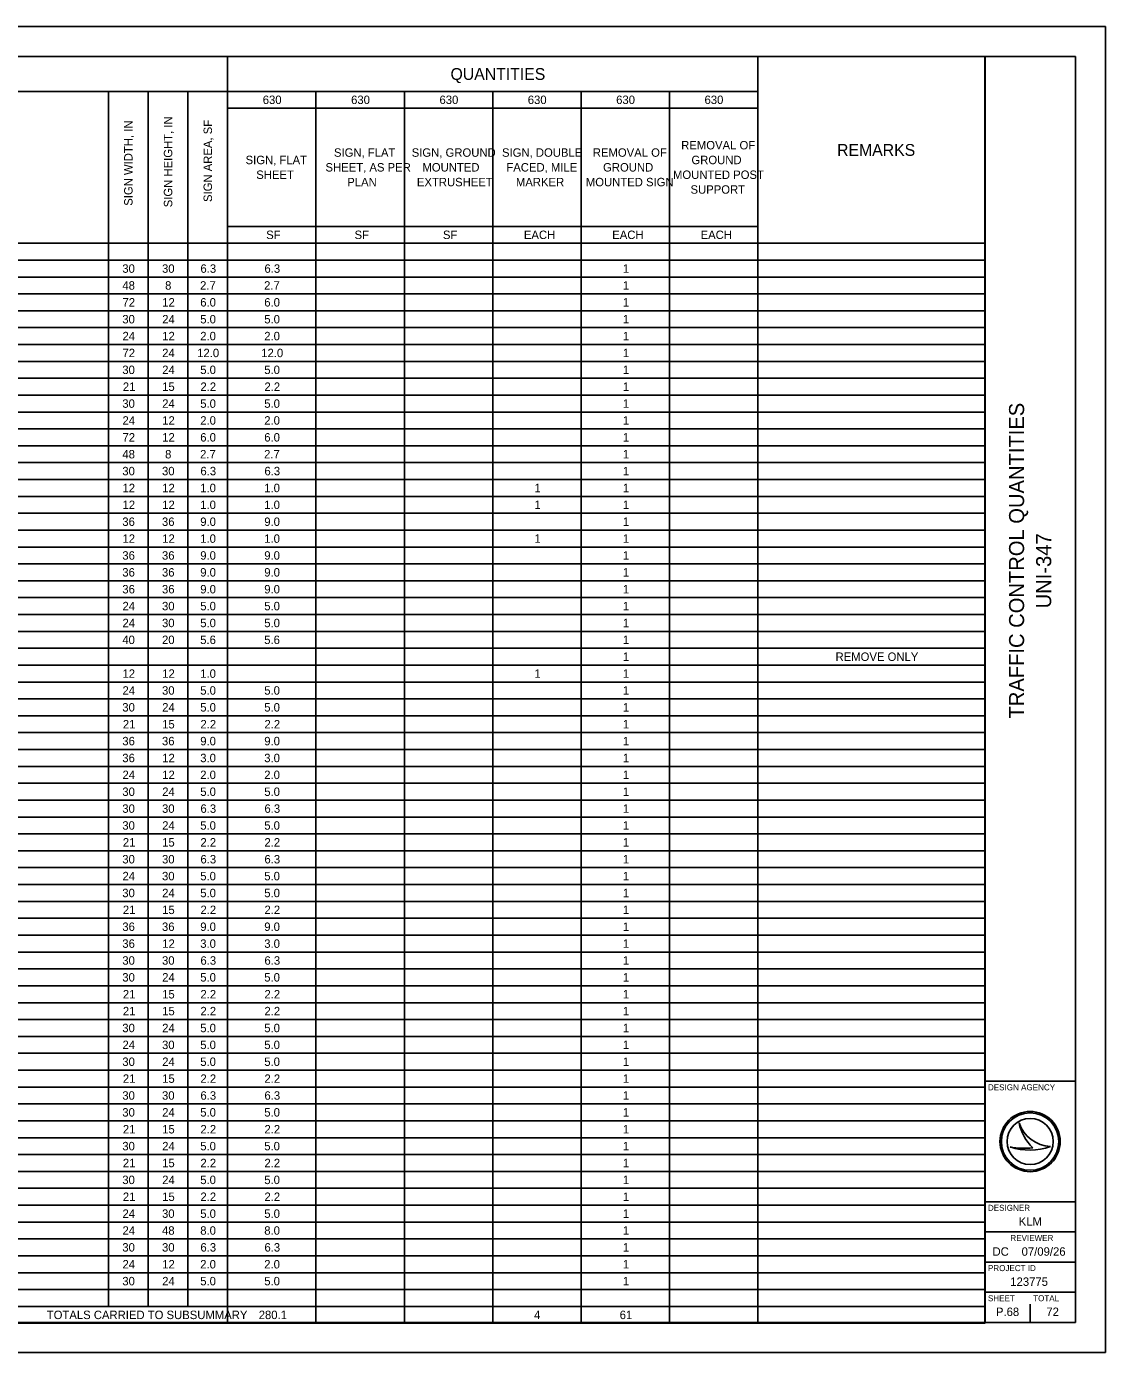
# Model space of a CAD drawing. Extents: x 0 to 34, y 0 to 22.
# Drawn here: x 16.1 to 34, y 0 to 22 of the extents above; entities that cross this region are included whole.
import ezdxf

# ---------------------------------------------------------------- set-up
doc = ezdxf.new("R2010")
doc.units = 0
for name, color, linetype in [('SH_Border', 7, 'Continuous'), ('SH_Cut_Line', 7, 'Continuous'), ('SH_Data', 7, 'Continuous'), ('SH_Text', 7, 'Continuous')]:
    doc.layers.add(name, color=color, linetype=linetype)

msp = doc.modelspace()

# ---------------------------------------------------------------- linework, layer by layer
at = {"layer": 'SH_Border'}
for p, q in [((32, 0.5), (32, 21.5)), ((32, 4.5), (33.5, 4.5)), ((32, 2.5), (33.5, 2.5)), ((32, 2), (33.5, 2)), ((32, 1.5), (33.5, 1.5)), ((32, 1), (33.5, 1))]:
    msp.add_line(p, q, dxfattribs=at)
msp.add_lwpolyline([(1.5, 21.5), (33.5, 21.5), (33.5, 0.5), (1.5, 0.5)], close=True, dxfattribs=at)
at = {"layer": 'SH_Cut_Line'}
msp.add_lwpolyline([(0, 0), (34, 0), (34, 22), (0, 22)], close=True, dxfattribs=at)
at = {"layer": 'SH_Data'}
for p, q in [((1.5, 21.5), (32.004, 21.5)), ((19.436, 21.5), (19.436, 0.484)), ((28.232, 21.5), (28.232, 0.484)), ((32.004, 21.5), (32.004, 0.484)), ((1.5, 20.924), (28.232, 20.924)), ((17.46, 20.924), (17.46, 0.764)), ((18.119, 20.924), (18.119, 0.764)), ((18.778, 20.924), (18.778, 0.764)), ((20.902, 20.924), (20.902, 0.484)), ((22.368, 20.924), (22.368, 0.484)), ((23.834, 20.924), (23.834, 0.484)), ((25.3, 20.924), (25.3, 0.484)), ((26.766, 20.924), (26.766, 0.484)), ((19.436, 20.644), (28.232, 20.644)), ((19.436, 18.684), (28.232, 18.684)), ((1.5, 18.404), (32.004, 18.404)), ((1.5, 18.124), (32.004, 18.124)), ((1.5, 17.844), (32.004, 17.844)), ((1.5, 17.564), (32.004, 17.564)), ((1.5, 17.284), (32.004, 17.284)), ((1.5, 17.004), (32.004, 17.004)), ((1.5, 16.724), (32.004, 16.724)), ((1.5, 16.444), (32.004, 16.444)), ((1.5, 16.164), (32.004, 16.164)), ((1.5, 15.884), (32.004, 15.884)), ((1.5, 15.604), (32.004, 15.604)), ((1.5, 15.324), (32.004, 15.324)), ((1.5, 15.044), (32.004, 15.044)), ((1.5, 14.764), (32.004, 14.764)), ((1.5, 14.484), (32.004, 14.484)), ((1.5, 14.204), (32.004, 14.204)), ((1.5, 13.924), (32.004, 13.924)), ((1.5, 13.644), (32.004, 13.644)), ((1.5, 13.364), (32.004, 13.364)), ((1.5, 13.084), (32.004, 13.084)), ((1.5, 12.804), (32.004, 12.804)), ((1.5, 12.524), (32.004, 12.524)), ((1.5, 12.244), (32.004, 12.244)), ((1.5, 11.964), (32.004, 11.964)), ((1.5, 11.684), (32.004, 11.684)), ((1.5, 11.404), (32.004, 11.404)), ((1.5, 11.124), (32.004, 11.124)), ((1.5, 10.844), (32.004, 10.844)), ((1.5, 10.564), (32.004, 10.564)), ((1.5, 10.284), (32.004, 10.284)), ((1.5, 10.004), (32.004, 10.004)), ((1.5, 9.724), (32.004, 9.724)), ((1.5, 9.444), (32.004, 9.444)), ((1.5, 9.164), (32.004, 9.164)), ((1.5, 8.884), (32.004, 8.884)), ((1.5, 8.604), (32.004, 8.604)), ((1.5, 8.324), (32.004, 8.324)), ((1.5, 8.044), (32.004, 8.044)), ((1.5, 7.764), (32.004, 7.764)), ((1.5, 7.484), (32.004, 7.484)), ((1.5, 7.204), (32.004, 7.204)), ((1.5, 6.924), (32.004, 6.924)), ((1.5, 6.644), (32.004, 6.644)), ((1.5, 6.364), (32.004, 6.364)), ((1.5, 6.084), (32.004, 6.084)), ((1.5, 5.804), (32.004, 5.804)), ((1.5, 5.524), (32.004, 5.524)), ((1.5, 5.244), (32.004, 5.244)), ((1.5, 4.964), (32.004, 4.964)), ((1.5, 4.684), (32.004, 4.684)), ((1.5, 4.404), (32.004, 4.404)), ((1.5, 4.124), (32.004, 4.124)), ((1.5, 3.844), (32.004, 3.844)), ((32.567, 3.81), (32.567, 3.81)), ((1.5, 3.564), (32.004, 3.564)), ((32.417, 3.41), (32.417, 3.41)), ((32.75, 3.5), (32.75, 3.5)), ((33.087, 3.419), (33.087, 3.419)), ((1.5, 3.284), (32.004, 3.284)), ((1.5, 3.004), (32.004, 3.004)), ((1.5, 2.724), (32.004, 2.724)), ((1.5, 2.444), (32.004, 2.444)), ((1.5, 2.164), (32.004, 2.164)), ((1.5, 1.884), (32.004, 1.884)), ((1.5, 1.604), (32.004, 1.604)), ((1.5, 1.324), (32.004, 1.324)), ((1.5, 1.044), (32.004, 1.044)), ((1.5, 0.764), (32.004, 0.764)), ((32.375, 0.675), (32.375, 0.675)), ((32.75, 0.5), (32.75, 0.8)), ((1.5, 0.484), (32.004, 0.484))]:
    msp.add_line(p, q, dxfattribs=at)
for radius in [0.5, 0.477, 0.477, 0.382]:
    msp.add_circle((32.75, 3.5), radius, dxfattribs=at)
for centre, radius, start, end in [((33.116, 3.998), 0.58, 198.9257, 198.9319), ((33.347, 3.97), 0.796, 191.6379, 191.6421), ((33.116, 3.998), 0.58, 198.9319, 267.1657), ((33.347, 3.97), 0.796, 191.6421, 226.0947), ((32.739, 4.37), 1.013, 251.4576, 290.0832), ((32.648, 4.654), 1.266, 259.4964, 259.4995), ((32.739, 4.37), 1.013, 251.4527, 251.4576), ((32.648, 4.654), 1.266, 259.4995, 276.6672)]:
    msp.add_arc(centre, radius, start, end, dxfattribs=at)

# ---------------------------------------------------------------- texts
for s, p in [('TRAFFIC CONTROL QUANTITIES', (32.65, 10.519)), ('UNI-347', (33.1, 12.346))]:
    msp.add_text(s, height=0.25, rotation=90, dxfattribs=at).set_placement(p)
for s, height, p in [('DESIGN AGENCY', 0.1, (32.05, 4.35)), ('DESIGNER', 0.1, (32.05, 2.35)), ('KLM', 0.14, (32.561, 2.105)), ('REVIEWER', 0.1, (32.422, 1.85)), ('DC', 0.14, (32.126, 1.605)), ('07/09/26', 0.14, (32.609, 1.605)), ('PROJECT ID', 0.1, (32.05, 1.35)), ('123775', 0.14, (32.421, 1.105)), ('SHEET', 0.1, (32.05, 0.85)), ('TOTAL', 0.1, (32.8, 0.85)), ('P.68', 0.14, (32.183, 0.605)), ('72', 0.14, (33.019, 0.605))]:
    msp.add_text(s, height=height, dxfattribs=at).set_placement(p)
at = {"layer": 'SH_Text'}
for s, height, p in [('QUANTITIES', 0.196, (23.134, 21.114)), ('630', 0.14, (20.019, 20.714)), ('630', 0.14, (21.485, 20.714)), ('630', 0.14, (22.951, 20.714)), ('630', 0.14, (24.416, 20.714)), ('630', 0.14, (25.882, 20.714)), ('630', 0.14, (27.348, 20.714)), ('REMOVAL OF ', 0.14, (26.961, 19.961)), ('REMARKS', 0.196, (29.547, 19.854)), ('SIGN, FLAT ', 0.14, (19.734, 19.716)), ('SIGN, FLAT ', 0.14, (21.2, 19.839)), ('SIGN, GROUND ', 0.14, (22.49, 19.839)), ('SIGN, DOUBLE ', 0.14, (23.988, 19.839)), ('REMOVAL OF ', 0.14, (25.495, 19.839)), ('GROUND ', 0.14, (27.131, 19.716)), ('SHEET', 0.14, (19.911, 19.471)), ('SHEET, AS PER ', 0.14, (21.06, 19.594)), ('MOUNTED ', 0.14, (22.668, 19.594)), ('FACED, MILE ', 0.14, (24.061, 19.594)), ('GROUND ', 0.14, (25.665, 19.594)), ('MOUNTED POST ', 0.14, (26.825, 19.471)), ('PLAN', 0.14, (21.421, 19.349)), ('EXTRUSHEET', 0.14, (22.576, 19.349)), ('MARKER', 0.14, (24.219, 19.349)), ('MOUNTED SIGN', 0.14, (25.379, 19.349)), ('SUPPORT', 0.14, (27.116, 19.226)), ('SF', 0.14, (20.076, 18.474)), ('SF', 0.14, (21.542, 18.474)), ('SF', 0.14, (23.008, 18.474)), ('EACH', 0.14, (24.351, 18.474)), ('EACH', 0.14, (25.817, 18.474)), ('EACH', 0.14, (27.283, 18.474)), ('30', 0.14, (17.689, 17.914)), ('30', 0.14, (18.348, 17.914)), ('6.3', 0.14, (18.985, 17.914)), ('6.3', 0.14, (20.047, 17.914)), ('1', 0.14, (25.992, 17.914)), ('48', 0.14, (17.69, 17.634)), ('8', 0.14, (18.399, 17.634)), ('2.7', 0.14, (18.979, 17.634)), ('2.7', 0.14, (20.041, 17.634)), ('1', 0.14, (25.992, 17.634)), ('72', 0.14, (17.692, 17.354)), ('12', 0.14, (18.351, 17.354)), ('6.0', 0.14, (18.982, 17.354)), ('6.0', 0.14, (20.044, 17.354)), ('1', 0.14, (25.992, 17.354)), ('30', 0.14, (17.689, 17.074)), ('24', 0.14, (18.351, 17.074)), ('5.0', 0.14, (18.982, 17.074)), ('5.0', 0.14, (20.044, 17.074)), ('1', 0.14, (25.992, 17.074)), ('24', 0.14, (17.692, 16.794)), ('12', 0.14, (18.351, 16.794)), ('2.0', 0.14, (18.982, 16.794)), ('2.0', 0.14, (20.044, 16.794)), ('1', 0.14, (25.992, 16.794)), ('72', 0.14, (17.692, 16.514)), ('24', 0.14, (18.351, 16.514)), ('12.0', 0.14, (18.931, 16.514)), ('12.0', 0.14, (19.994, 16.514)), ('1', 0.14, (25.992, 16.514)), ('30', 0.14, (17.689, 16.234)), ('24', 0.14, (18.351, 16.234)), ('5.0', 0.14, (18.982, 16.234)), ('5.0', 0.14, (20.044, 16.234)), ('1', 0.14, (25.992, 16.234)), ('21', 0.14, (17.698, 15.954)), ('15', 0.14, (18.35, 15.954)), ('2.2', 0.14, (18.985, 15.954)), ('2.2', 0.14, (20.047, 15.954)), ('1', 0.14, (25.992, 15.954)), ('30', 0.14, (17.689, 15.674)), ('24', 0.14, (18.351, 15.674)), ('5.0', 0.14, (18.982, 15.674)), ('5.0', 0.14, (20.044, 15.674)), ('1', 0.14, (25.992, 15.674)), ('24', 0.14, (17.692, 15.394)), ('12', 0.14, (18.351, 15.394)), ('2.0', 0.14, (18.982, 15.394)), ('2.0', 0.14, (20.044, 15.394)), ('1', 0.14, (25.992, 15.394)), ('72', 0.14, (17.692, 15.114)), ('12', 0.14, (18.351, 15.114)), ('6.0', 0.14, (18.982, 15.114)), ('6.0', 0.14, (20.044, 15.114)), ('1', 0.14, (25.992, 15.114)), ('48', 0.14, (17.69, 14.834)), ('8', 0.14, (18.399, 14.834)), ('2.7', 0.14, (18.979, 14.834)), ('2.7', 0.14, (20.041, 14.834)), ('1', 0.14, (25.992, 14.834)), ('30', 0.14, (17.689, 14.554)), ('30', 0.14, (18.348, 14.554)), ('6.3', 0.14, (18.985, 14.554)), ('6.3', 0.14, (20.047, 14.554)), ('1', 0.14, (25.992, 14.554)), ('12', 0.14, (17.692, 14.274)), ('12', 0.14, (18.351, 14.274)), ('1.0', 0.14, (18.982, 14.274)), ('1.0', 0.14, (20.044, 14.274)), ('1', 0.14, (24.526, 14.274)), ('1', 0.14, (25.992, 14.274)), ('12', 0.14, (17.692, 13.994)), ('12', 0.14, (18.351, 13.994)), ('1.0', 0.14, (18.982, 13.994)), ('1.0', 0.14, (20.044, 13.994)), ('1', 0.14, (24.526, 13.994)), ('1', 0.14, (25.992, 13.994)), ('36', 0.14, (17.689, 13.714)), ('36', 0.14, (18.347, 13.714)), ('9.0', 0.14, (18.982, 13.714)), ('9.0', 0.14, (20.044, 13.714)), ('1', 0.14, (25.992, 13.714)), ('12', 0.14, (17.692, 13.434)), ('12', 0.14, (18.351, 13.434)), ('1.0', 0.14, (18.982, 13.434)), ('1.0', 0.14, (20.044, 13.434)), ('1', 0.14, (24.526, 13.434)), ('1', 0.14, (25.992, 13.434)), ('36', 0.14, (17.689, 13.154)), ('36', 0.14, (18.347, 13.154)), ('9.0', 0.14, (18.982, 13.154)), ('9.0', 0.14, (20.044, 13.154)), ('1', 0.14, (25.992, 13.154)), ('36', 0.14, (17.689, 12.874)), ('36', 0.14, (18.347, 12.874)), ('9.0', 0.14, (18.982, 12.874)), ('9.0', 0.14, (20.044, 12.874)), ('1', 0.14, (25.992, 12.874)), ('36', 0.14, (17.689, 12.594)), ('36', 0.14, (18.347, 12.594)), ('9.0', 0.14, (18.982, 12.594)), ('9.0', 0.14, (20.044, 12.594)), ('1', 0.14, (25.992, 12.594)), ('24', 0.14, (17.692, 12.314)), ('30', 0.14, (18.348, 12.314)), ('5.0', 0.14, (18.982, 12.314)), ('5.0', 0.14, (20.044, 12.314)), ('1', 0.14, (25.992, 12.314)), ('24', 0.14, (17.692, 12.034)), ('30', 0.14, (18.348, 12.034)), ('5.0', 0.14, (18.982, 12.034)), ('5.0', 0.14, (20.044, 12.034)), ('1', 0.14, (25.992, 12.034)), ('40', 0.14, (17.689, 11.754)), ('20', 0.14, (18.348, 11.754)), ('5.6', 0.14, (18.981, 11.754)), ('5.6', 0.14, (20.043, 11.754)), ('1', 0.14, (25.992, 11.754)), ('1', 0.14, (25.992, 11.474)), ('REMOVE ONLY', 0.14, (29.522, 11.474)), ('12', 0.14, (17.692, 11.194)), ('12', 0.14, (18.351, 11.194)), ('1.0', 0.14, (18.982, 11.194)), ('1', 0.14, (24.526, 11.194)), ('1', 0.14, (25.992, 11.194)), ('24', 0.14, (17.692, 10.914)), ('30', 0.14, (18.348, 10.914)), ('5.0', 0.14, (18.982, 10.914)), ('5.0', 0.14, (20.044, 10.914)), ('1', 0.14, (25.992, 10.914)), ('30', 0.14, (17.689, 10.634)), ('24', 0.14, (18.351, 10.634)), ('5.0', 0.14, (18.982, 10.634)), ('5.0', 0.14, (20.044, 10.634)), ('1', 0.14, (25.992, 10.634)), ('21', 0.14, (17.698, 10.354)), ('15', 0.14, (18.35, 10.354)), ('2.2', 0.14, (18.985, 10.354)), ('2.2', 0.14, (20.047, 10.354)), ('1', 0.14, (25.992, 10.354)), ('36', 0.14, (17.689, 10.074)), ('36', 0.14, (18.347, 10.074)), ('9.0', 0.14, (18.982, 10.074)), ('9.0', 0.14, (20.044, 10.074)), ('1', 0.14, (25.992, 10.074)), ('36', 0.14, (17.689, 9.794)), ('12', 0.14, (18.351, 9.794)), ('3.0', 0.14, (18.982, 9.794)), ('3.0', 0.14, (20.044, 9.794)), ('1', 0.14, (25.992, 9.794)), ('24', 0.14, (17.692, 9.514)), ('12', 0.14, (18.351, 9.514)), ('2.0', 0.14, (18.982, 9.514)), ('2.0', 0.14, (20.044, 9.514)), ('1', 0.14, (25.992, 9.514)), ('30', 0.14, (17.689, 9.234)), ('24', 0.14, (18.351, 9.234)), ('5.0', 0.14, (18.982, 9.234)), ('5.0', 0.14, (20.044, 9.234)), ('1', 0.14, (25.992, 9.234)), ('30', 0.14, (17.689, 8.954)), ('30', 0.14, (18.348, 8.954)), ('6.3', 0.14, (18.985, 8.954)), ('6.3', 0.14, (20.047, 8.954)), ('1', 0.14, (25.992, 8.954)), ('30', 0.14, (17.689, 8.674)), ('24', 0.14, (18.351, 8.674)), ('5.0', 0.14, (18.982, 8.674)), ('5.0', 0.14, (20.044, 8.674)), ('1', 0.14, (25.992, 8.674)), ('21', 0.14, (17.698, 8.394)), ('15', 0.14, (18.35, 8.394)), ('2.2', 0.14, (18.985, 8.394)), ('2.2', 0.14, (20.047, 8.394)), ('1', 0.14, (25.992, 8.394)), ('30', 0.14, (17.689, 8.114)), ('30', 0.14, (18.348, 8.114)), ('6.3', 0.14, (18.985, 8.114)), ('6.3', 0.14, (20.047, 8.114)), ('1', 0.14, (25.992, 8.114)), ('24', 0.14, (17.692, 7.834)), ('30', 0.14, (18.348, 7.834)), ('5.0', 0.14, (18.982, 7.834)), ('5.0', 0.14, (20.044, 7.834)), ('1', 0.14, (25.992, 7.834)), ('30', 0.14, (17.689, 7.554)), ('24', 0.14, (18.351, 7.554)), ('5.0', 0.14, (18.982, 7.554)), ('5.0', 0.14, (20.044, 7.554)), ('1', 0.14, (25.992, 7.554)), ('21', 0.14, (17.698, 7.274)), ('15', 0.14, (18.35, 7.274)), ('2.2', 0.14, (18.985, 7.274)), ('2.2', 0.14, (20.047, 7.274)), ('1', 0.14, (25.992, 7.274)), ('36', 0.14, (17.689, 6.994)), ('36', 0.14, (18.347, 6.994)), ('9.0', 0.14, (18.982, 6.994)), ('9.0', 0.14, (20.044, 6.994)), ('1', 0.14, (25.992, 6.994)), ('36', 0.14, (17.689, 6.714)), ('12', 0.14, (18.351, 6.714)), ('3.0', 0.14, (18.982, 6.714)), ('3.0', 0.14, (20.044, 6.714)), ('1', 0.14, (25.992, 6.714)), ('30', 0.14, (17.689, 6.434)), ('30', 0.14, (18.348, 6.434)), ('6.3', 0.14, (18.985, 6.434)), ('6.3', 0.14, (20.047, 6.434)), ('1', 0.14, (25.992, 6.434)), ('30', 0.14, (17.689, 6.154)), ('24', 0.14, (18.351, 6.154)), ('5.0', 0.14, (18.982, 6.154)), ('5.0', 0.14, (20.044, 6.154)), ('1', 0.14, (25.992, 6.154)), ('21', 0.14, (17.698, 5.874)), ('15', 0.14, (18.35, 5.874)), ('2.2', 0.14, (18.985, 5.874)), ('2.2', 0.14, (20.047, 5.874)), ('1', 0.14, (25.992, 5.874)), ('21', 0.14, (17.698, 5.594)), ('15', 0.14, (18.35, 5.594)), ('2.2', 0.14, (18.985, 5.594)), ('2.2', 0.14, (20.047, 5.594)), ('1', 0.14, (25.992, 5.594)), ('30', 0.14, (17.689, 5.314)), ('24', 0.14, (18.351, 5.314)), ('5.0', 0.14, (18.982, 5.314)), ('5.0', 0.14, (20.044, 5.314)), ('1', 0.14, (25.992, 5.314)), ('24', 0.14, (17.692, 5.034)), ('30', 0.14, (18.348, 5.034)), ('5.0', 0.14, (18.982, 5.034)), ('5.0', 0.14, (20.044, 5.034)), ('1', 0.14, (25.992, 5.034)), ('30', 0.14, (17.689, 4.754)), ('24', 0.14, (18.351, 4.754)), ('5.0', 0.14, (18.982, 4.754)), ('5.0', 0.14, (20.044, 4.754)), ('1', 0.14, (25.992, 4.754)), ('21', 0.14, (17.698, 4.474)), ('15', 0.14, (18.35, 4.474)), ('2.2', 0.14, (18.985, 4.474)), ('2.2', 0.14, (20.047, 4.474)), ('1', 0.14, (25.992, 4.474)), ('30', 0.14, (17.689, 4.194)), ('30', 0.14, (18.348, 4.194)), ('6.3', 0.14, (18.985, 4.194)), ('6.3', 0.14, (20.047, 4.194)), ('1', 0.14, (25.992, 4.194)), ('30', 0.14, (17.689, 3.914)), ('24', 0.14, (18.351, 3.914)), ('5.0', 0.14, (18.982, 3.914)), ('5.0', 0.14, (20.044, 3.914)), ('1', 0.14, (25.992, 3.914)), ('21', 0.14, (17.698, 3.634)), ('15', 0.14, (18.35, 3.634)), ('2.2', 0.14, (18.985, 3.634)), ('2.2', 0.14, (20.047, 3.634)), ('1', 0.14, (25.992, 3.634)), ('30', 0.14, (17.689, 3.354)), ('24', 0.14, (18.351, 3.354)), ('5.0', 0.14, (18.982, 3.354)), ('5.0', 0.14, (20.044, 3.354)), ('1', 0.14, (25.992, 3.354)), ('21', 0.14, (17.698, 3.074)), ('15', 0.14, (18.35, 3.074)), ('2.2', 0.14, (18.985, 3.074)), ('2.2', 0.14, (20.047, 3.074)), ('1', 0.14, (25.992, 3.074)), ('30', 0.14, (17.689, 2.794)), ('24', 0.14, (18.351, 2.794)), ('5.0', 0.14, (18.982, 2.794)), ('5.0', 0.14, (20.044, 2.794)), ('1', 0.14, (25.992, 2.794)), ('21', 0.14, (17.698, 2.514)), ('15', 0.14, (18.35, 2.514)), ('2.2', 0.14, (18.985, 2.514)), ('2.2', 0.14, (20.047, 2.514)), ('1', 0.14, (25.992, 2.514)), ('24', 0.14, (17.692, 2.234)), ('30', 0.14, (18.348, 2.234)), ('5.0', 0.14, (18.982, 2.234)), ('5.0', 0.14, (20.044, 2.234)), ('1', 0.14, (25.992, 2.234)), ('24', 0.14, (17.692, 1.954)), ('48', 0.14, (18.348, 1.954)), ('8.0', 0.14, (18.982, 1.954)), ('8.0', 0.14, (20.044, 1.954)), ('1', 0.14, (25.992, 1.954)), ('30', 0.14, (17.689, 1.674)), ('30', 0.14, (18.348, 1.674)), ('6.3', 0.14, (18.985, 1.674)), ('6.3', 0.14, (20.047, 1.674)), ('1', 0.14, (25.992, 1.674)), ('24', 0.14, (17.692, 1.394)), ('12', 0.14, (18.351, 1.394)), ('2.0', 0.14, (18.982, 1.394)), ('2.0', 0.14, (20.044, 1.394)), ('1', 0.14, (25.992, 1.394)), ('30', 0.14, (17.689, 1.114)), ('24', 0.14, (18.351, 1.114)), ('5.0', 0.14, (18.982, 1.114)), ('5.0', 0.14, (20.044, 1.114)), ('1', 0.14, (25.992, 1.114)), ('TOTALS CARRIED TO SUBSUMMARY', 0.14, (16.436, 0.554)), ('280.1', 0.14, (19.952, 0.554)), ('4', 0.14, (24.52, 0.554)), ('61', 0.14, (25.941, 0.554))]:
    msp.add_text(s, height=height, dxfattribs=at).set_placement(p)
for s, p in [('SIGN HEIGHT, IN', (18.518, 19.001)), ('SIGN WIDTH, IN', (17.859, 19.026)), ('SIGN AREA, SF', (19.177, 19.088))]:
    msp.add_text(s, height=0.14, rotation=90, dxfattribs=at).set_placement(p)

doc.saveas('drawing.dxf')
